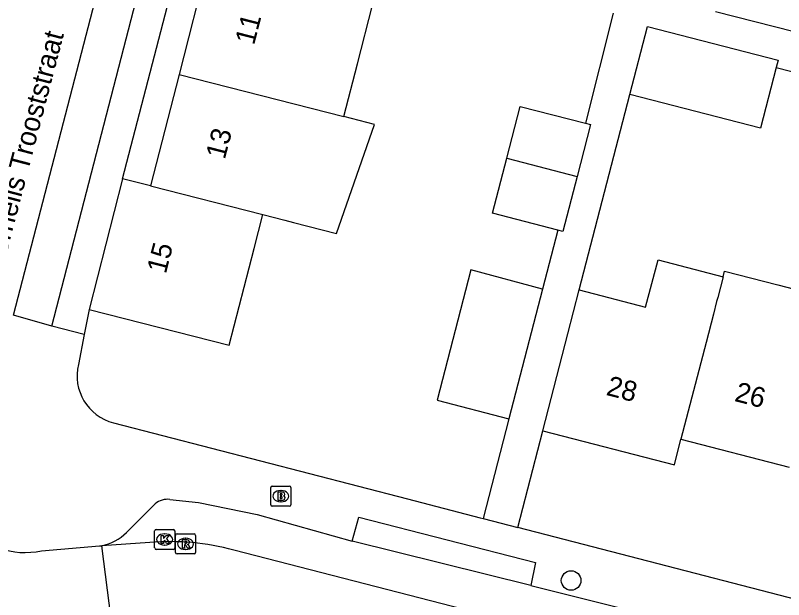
# Model space of a CAD drawing. Extents: x 163686 to 164493, y 382719 to 383870.
# Drawn here: x 164044.47 to 164082.89, y 383167.24 to 383196.46 of the extents above; entities that cross this region are included whole.
import ezdxf

# ---------------------------------------------------------------- set-up
doc = ezdxf.new("R2010")
doc.units = 0
for name, color, linetype in [('IMGEO_Boom', 7, 'Continuous'), ('IMGEO_Brandkraan', 7, 'Continuous'), ('IMGEO_Kolk', 7, 'Continuous'), ('IMGEO_Openbare_ruimte_label', 7, 'Continuous'), ('IMGEO_Pand', 7, 'Continuous'), ('IMGEO_Pand_nummerreeks', 7, 'Continuous'), ('IMGEO_Rijbaan_lokaal_open', 7, 'Continuous'), ('IMGEO_Rioolput', 7, 'Continuous'), ('IMGEO_Voetpad_open', 7, 'Continuous')]:
    doc.layers.add(name, color=color, linetype=linetype)

msp = doc.modelspace()

# ---------------------------------------------------------------- linework, layer by layer
at = {"layer": 'IMGEO_Boom'}
msp.add_circle((164072.259, 383168.199), 0.489, dxfattribs=at)
at = {"layer": 'IMGEO_Brandkraan'}
for p, q in [((164057.24, 383171.99), (164057.24, 383172.842)), ((164057.315, 383172.916), (164058.167, 383172.916)), ((164057.728, 383172.696), (164057.753, 383172.696)), ((164058.241, 383172.842), (164058.241, 383171.99)), ((164058.167, 383171.916), (164057.315, 383171.916)), ((164057.751, 383172.136), (164057.726, 383172.136))]:
    msp.add_line(p, q, dxfattribs=at)
for points in [[(164057.24, 383171.99), (164057.24, 383172.842)], [(164057.315, 383172.916), (164058.167, 383172.916)], [(164058.241, 383172.842), (164058.241, 383171.99)], [(164057.588, 383172.616), (164057.588, 383172.216), (164057.801, 383172.216)], [(164057.819, 383172.616), (164057.588, 383172.616)], [(164057.767, 383172.535), (164057.713, 383172.535), (164057.713, 383172.459)], [(164057.713, 383172.459), (164057.766, 383172.459)], [(164057.775, 383172.383), (164057.713, 383172.383), (164057.713, 383172.302)], [(164057.713, 383172.302), (164057.775, 383172.302)], [(164058.167, 383171.916), (164057.315, 383171.916)]]:
    msp.add_lwpolyline(points, dxfattribs=at)
for centre, radius, start, end in [((164057.317, 383172.84), 0.0765, 91.552, 178.448), ((164057.317, 383172.84), 0.0765, 91.552, 178.448), ((164058.165, 383172.84), 0.0765, 1.552, 88.448), ((164058.165, 383172.84), 0.0765, 1.552, 88.448), ((164057.768, 383172.497), 0.0379, 267.8285, 90.9355), ((164057.776, 383172.342), 0.0404, 269.8759, 90.5077), ((164057.823, 383172.471), 0.145, 59.4692, 91.5367), ((164057.848, 383172.518), 0.0922, 285.5137, 58.1501), ((164057.853, 383172.326), 0.105, 301.3115, 78.989), ((164057.317, 383171.992), 0.0765, 181.552, 268.448), ((164057.317, 383171.992), 0.0765, 181.552, 268.448), ((164057.807, 383172.467), 0.251, 268.6676, 293.5347), ((164058.165, 383171.992), 0.0765, 271.552, 358.448), ((164058.165, 383171.992), 0.0765, 271.552, 358.448)]:
    msp.add_arc(centre, radius, start, end, dxfattribs=at)
for centre, major_axis, ratio, start_param, end_param in [((164057.727, 383172.416), (-0.387, 0.002), 0.722429, 4.712389, 7.853982), ((164057.752, 383172.416), (-0.39, 0.002), 0.717154, 1.570796, 4.712389)]:
    msp.add_ellipse(centre, major_axis=major_axis, ratio=ratio, start_param=start_param, end_param=end_param, dxfattribs=at)
at = {"layer": 'IMGEO_Kolk'}
for p, q in [((164051.507, 383170.751), (164052.359, 383170.751)), ((164051.432, 383169.825), (164051.432, 383170.677)), ((164051.92, 383170.531), (164051.945, 383170.531)), ((164052.433, 383170.677), (164052.433, 383169.825)), ((164051.943, 383169.971), (164051.918, 383169.971)), ((164052.359, 383169.751), (164051.507, 383169.751))]:
    msp.add_line(p, q, dxfattribs=at)
for points in [[(164051.507, 383170.751), (164052.359, 383170.751)], [(164051.432, 383169.825), (164051.432, 383170.677)], [(164051.753, 383170.451), (164051.876, 383170.451), (164051.876, 383170.3), (164052.006, 383170.451), (164052.17, 383170.451), (164052.024, 383170.3), (164052.177, 383170.051), (164052.025, 383170.051), (164051.94, 383170.215), (164051.876, 383170.148), (164051.876, 383170.051), (164051.753, 383170.051), (164051.753, 383170.451)], [(164052.433, 383170.677), (164052.433, 383169.825)], [(164052.359, 383169.751), (164051.507, 383169.751)]]:
    msp.add_lwpolyline(points, dxfattribs=at)
for centre, start, end in [((164051.509, 383170.675), 91.552, 178.448), ((164051.509, 383170.675), 91.552, 178.448), ((164052.357, 383170.675), 1.552, 88.448), ((164052.357, 383170.675), 1.552, 88.448), ((164051.509, 383169.827), 181.552, 268.448), ((164051.509, 383169.827), 181.552, 268.448), ((164052.357, 383169.827), 271.552, 358.448), ((164052.357, 383169.827), 271.552, 358.448)]:
    msp.add_arc(centre, 0.0765, start, end, dxfattribs=at)
for centre, major_axis, ratio, start_param, end_param in [((164051.919, 383170.251), (-0.387, 0.002), 0.722429, 4.712389, 7.853982), ((164051.944, 383170.251), (-0.39, 0.002), 0.717154, 1.570796, 4.712389)]:
    msp.add_ellipse(centre, major_axis=major_axis, ratio=ratio, start_param=start_param, end_param=end_param, dxfattribs=at)
at = {"layer": 'IMGEO_Pand'}
for points in [[(164054.078, 383199.082), (164052.651, 383193.505)], [(164060.897, 383191.395), (164061.571, 383194.028), (164062.324, 383196.971), (164061.24, 383197.249)], [(164075.193, 383192.504), (164076.072, 383195.903), (164082.614, 383194.21), (164082.52, 383193.849)], [(164082.52, 383193.849), (164081.734, 383190.811), (164075.193, 383192.504)], [(164052.651, 383193.505), (164051.225, 383187.934)], [(164052.651, 383193.505), (164060.897, 383191.395)], [(164069.042, 383189.311), (164069.718, 383191.906), (164072.979, 383191.058)], [(164056.836, 383186.499), (164057.943, 383186.216), (164058.38, 383186.1), (164060.523, 383185.552), (164062.431, 383191.003), (164060.897, 383191.395)], [(164072.979, 383191.058), (164073.236, 383190.991), (164072.56, 383188.395)], [(164071.592, 383185.717), (164068.328, 383186.566), (164069.042, 383189.311)], [(164069.042, 383189.311), (164072.56, 383188.395)], [(164072.56, 383188.395), (164071.846, 383185.651), (164071.592, 383185.717)], [(164049.831, 383188.29), (164048.158, 383181.754)], [(164051.225, 383187.934), (164049.831, 383188.29)], [(164051.225, 383187.934), (164056.836, 383186.499)], [(164048.158, 383181.754), (164055.163, 383179.962), (164056.403, 383184.806), (164056.836, 383186.499)], [(164072.664, 383182.727), (164075.987, 383181.867), (164076.606, 383184.236), (164079.857, 383183.387)], [(164070.824, 383182.771), (164067.247, 383183.731), (164065.561, 383177.211), (164069.146, 383176.283)], [(164079.857, 383183.387), (164079.589, 383182.348), (164079.537, 383182.151), (164079.373, 383181.515), (164079.006, 383180.098), (164077.754, 383175.259)], [(164079.857, 383183.387), (164079.929, 383183.666), (164082.597, 383182.976), (164085.343, 383182.266)], [(164070.824, 383182.771), (164069.146, 383176.283)], [(164070.844, 383175.69), (164072.096, 383180.531), (164072.664, 383182.727)], [(164070.844, 383175.69), (164077.424, 383173.987), (164077.754, 383175.259)], [(164077.754, 383175.259), (164083.161, 383173.86)]]:
    msp.add_lwpolyline(points, dxfattribs=at)
at = {"layer": 'IMGEO_Rijbaan_lokaal_open'}
for points in [[(164044.371, 383181.473), (164050.04, 383203.31), (164056.197, 383227.065), (164056.397, 383227.867)], [(164051.188, 383170.099), (164048.792, 383169.933)], [(164045.773, 383169.687), (164048.677, 383169.925), (164048.792, 383169.933)], [(164049.254, 383166.286), (164048.792, 383169.933)], [(164176.893, 383138.284), (164107.356, 383156.336), (164055.386, 383169.723)]]:
    msp.add_lwpolyline(points, dxfattribs=at)
for centre, radius, start, end in [((164044.957, 383173.344), 3.747, 216.962, 282.5799), ((164052.211, 383157.896), 12.245, 74.9721, 94.7916)]:
    msp.add_arc(centre, radius, start, end, dxfattribs=at)
at = {"layer": 'IMGEO_Rioolput'}
for p, q in [((164052.475, 383169.603), (164052.475, 383170.455)), ((164052.55, 383170.529), (164053.402, 383170.529)), ((164053.476, 383170.455), (164053.476, 383169.603)), ((164052.963, 383170.309), (164052.988, 383170.309)), ((164052.986, 383169.749), (164052.961, 383169.749)), ((164053.402, 383169.529), (164052.55, 383169.529))]:
    msp.add_line(p, q, dxfattribs=at)
for points in [[(164052.475, 383169.603), (164052.475, 383170.455)], [(164052.55, 383170.529), (164053.402, 383170.529)], [(164053.476, 383170.455), (164053.476, 383169.603)], [(164053.064, 383170.227), (164052.812, 383170.229), (164052.812, 383169.829)], [(164052.812, 383169.829), (164052.936, 383169.829), (164052.936, 383169.991), (164052.947, 383169.991)], [(164052.99, 383170.148), (164052.936, 383170.148), (164052.936, 383170.067)], [(164052.936, 383170.067), (164052.988, 383170.067)], [(164052.994, 383169.962), (164053.065, 383169.829), (164053.205, 383169.829), (164053.14, 383169.955)], [(164053.402, 383169.529), (164052.55, 383169.529)]]:
    msp.add_lwpolyline(points, dxfattribs=at)
for centre, radius, start, end in [((164052.552, 383170.453), 0.0765, 91.552, 178.448), ((164052.552, 383170.453), 0.0765, 91.552, 178.448), ((164053.4, 383170.453), 0.0765, 1.552, 88.448), ((164053.4, 383170.453), 0.0765, 1.552, 88.448), ((164052.946, 383169.938), 0.0533, 26.0293, 88.6989), ((164052.972, 383170.256), 0.19, 274.7715, 282.9687), ((164052.996, 383170.052), 0.0964, 77.0061, 93.1865), ((164053.01, 383170.109), 0.0378, 276.6634, 79.6772), ((164053.063, 383170.117), 0.109, 350.3612, 89.416), ((164053.061, 383170.117), 0.112, 277.5842, 350.9817), ((164053.045, 383169.902), 0.108, 29.5134, 73.7905), ((164052.552, 383169.605), 0.0765, 181.552, 268.448), ((164052.552, 383169.605), 0.0765, 181.552, 268.448), ((164053.4, 383169.605), 0.0765, 271.552, 358.448), ((164053.4, 383169.605), 0.0765, 271.552, 358.448)]:
    msp.add_arc(centre, radius, start, end, dxfattribs=at)
for centre, major_axis, ratio, start_param, end_param in [((164052.962, 383170.029), (-0.387, 0.002), 0.722429, 4.712389, 7.853982), ((164052.987, 383170.029), (-0.39, 0.002), 0.717154, 1.570796, 4.712389)]:
    msp.add_ellipse(centre, major_axis=major_axis, ratio=ratio, start_param=start_param, end_param=end_param, dxfattribs=at)
at = {"layer": 'IMGEO_Voetpad_open'}
for points in [[(164046.293, 383180.913), (164058.315, 383227.381), (164056.397, 383227.867)], [(164049.831, 383188.29), (164058.584, 383221.924)], [(164074.358, 383196.566), (164072.979, 383191.058)], [(164079.473, 383196.643), (164086.359, 383194.903)], [(164082.52, 383193.849), (164085.826, 383192.994)], [(164072.664, 383182.727), (164075.193, 383192.504)], [(164071.592, 383185.717), (164070.824, 383182.771)], [(164046.293, 383180.913), (164044.371, 383181.473)], [(164048.158, 383181.754), (164047.91, 383180.492)], [(164047.91, 383180.492), (164046.293, 383180.913)], [(164047.91, 383180.492), (164047.617, 383179.004)], [(164049.375, 383176.083), (164064.079, 383172.277), (164067.709, 383171.337), (164067.856, 383171.299)], [(164069.146, 383176.283), (164067.856, 383171.299)], [(164069.591, 383170.85), (164070.844, 383175.69)], [(164052.199, 383172.252), (164053.618, 383172.103), (164056.554, 383171.505), (164061.314, 383170.172)], [(164050.02, 383170.593), (164051.458, 383172.033)], [(164061.314, 383170.172), (164061.645, 383171.365), (164070.479, 383169.093), (164070.239, 383167.953)], [(164067.856, 383171.299), (164069.591, 383170.85)], [(164113.082, 383159.592), (164113.066, 383159.596), (164109.777, 383160.447), (164069.591, 383170.85)], [(164070.239, 383167.953), (164061.314, 383170.172)], [(164070.239, 383167.953), (164079.713, 383165.583), (164097.462, 383160.961), (164107.839, 383158.274)]]:
    msp.add_lwpolyline(points, dxfattribs=at)
for centre, radius, start, end in [((164049.981, 383178.437), 2.431, 166.5204, 255.5627), ((164052.09, 383171.257), 1.001, 83.7679, 129.1618), ((164048.239, 383172.435), 2.562, 282.4686, 314.0438)]:
    msp.add_arc(centre, radius, start, end, dxfattribs=at)

# ---------------------------------------------------------------- texts
at = {"layer": 'IMGEO_Openbare_ruimte_label'}
msp.add_text('Cornelis Trooststraat', height=1, rotation=75.3381, dxfattribs=at).set_placement((164043.758, 383183.51))
at = {"layer": 'IMGEO_Pand_nummerreeks'}
for s, rotation, p in [('11', 75.6419, (164056.403, 383194.936)), ('13', 75.6419, (164054.939, 383189.215)), ('15', 75.6419, (164051.99, 383183.497)), ('28', 345.487, (164073.969, 383177.485)), ('26', 345.4927, (164080.386, 383177.181))]:
    msp.add_text(s, height=1, rotation=rotation, dxfattribs=at).set_placement(p)

doc.saveas('drawing.dxf')
